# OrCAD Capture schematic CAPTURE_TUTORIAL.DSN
size A; title: Capture Walkthrough; rev: A; company: EMA Design Automation; note: EMA-12345678; note: 225 Tech park Dr; note: Rochester, NY
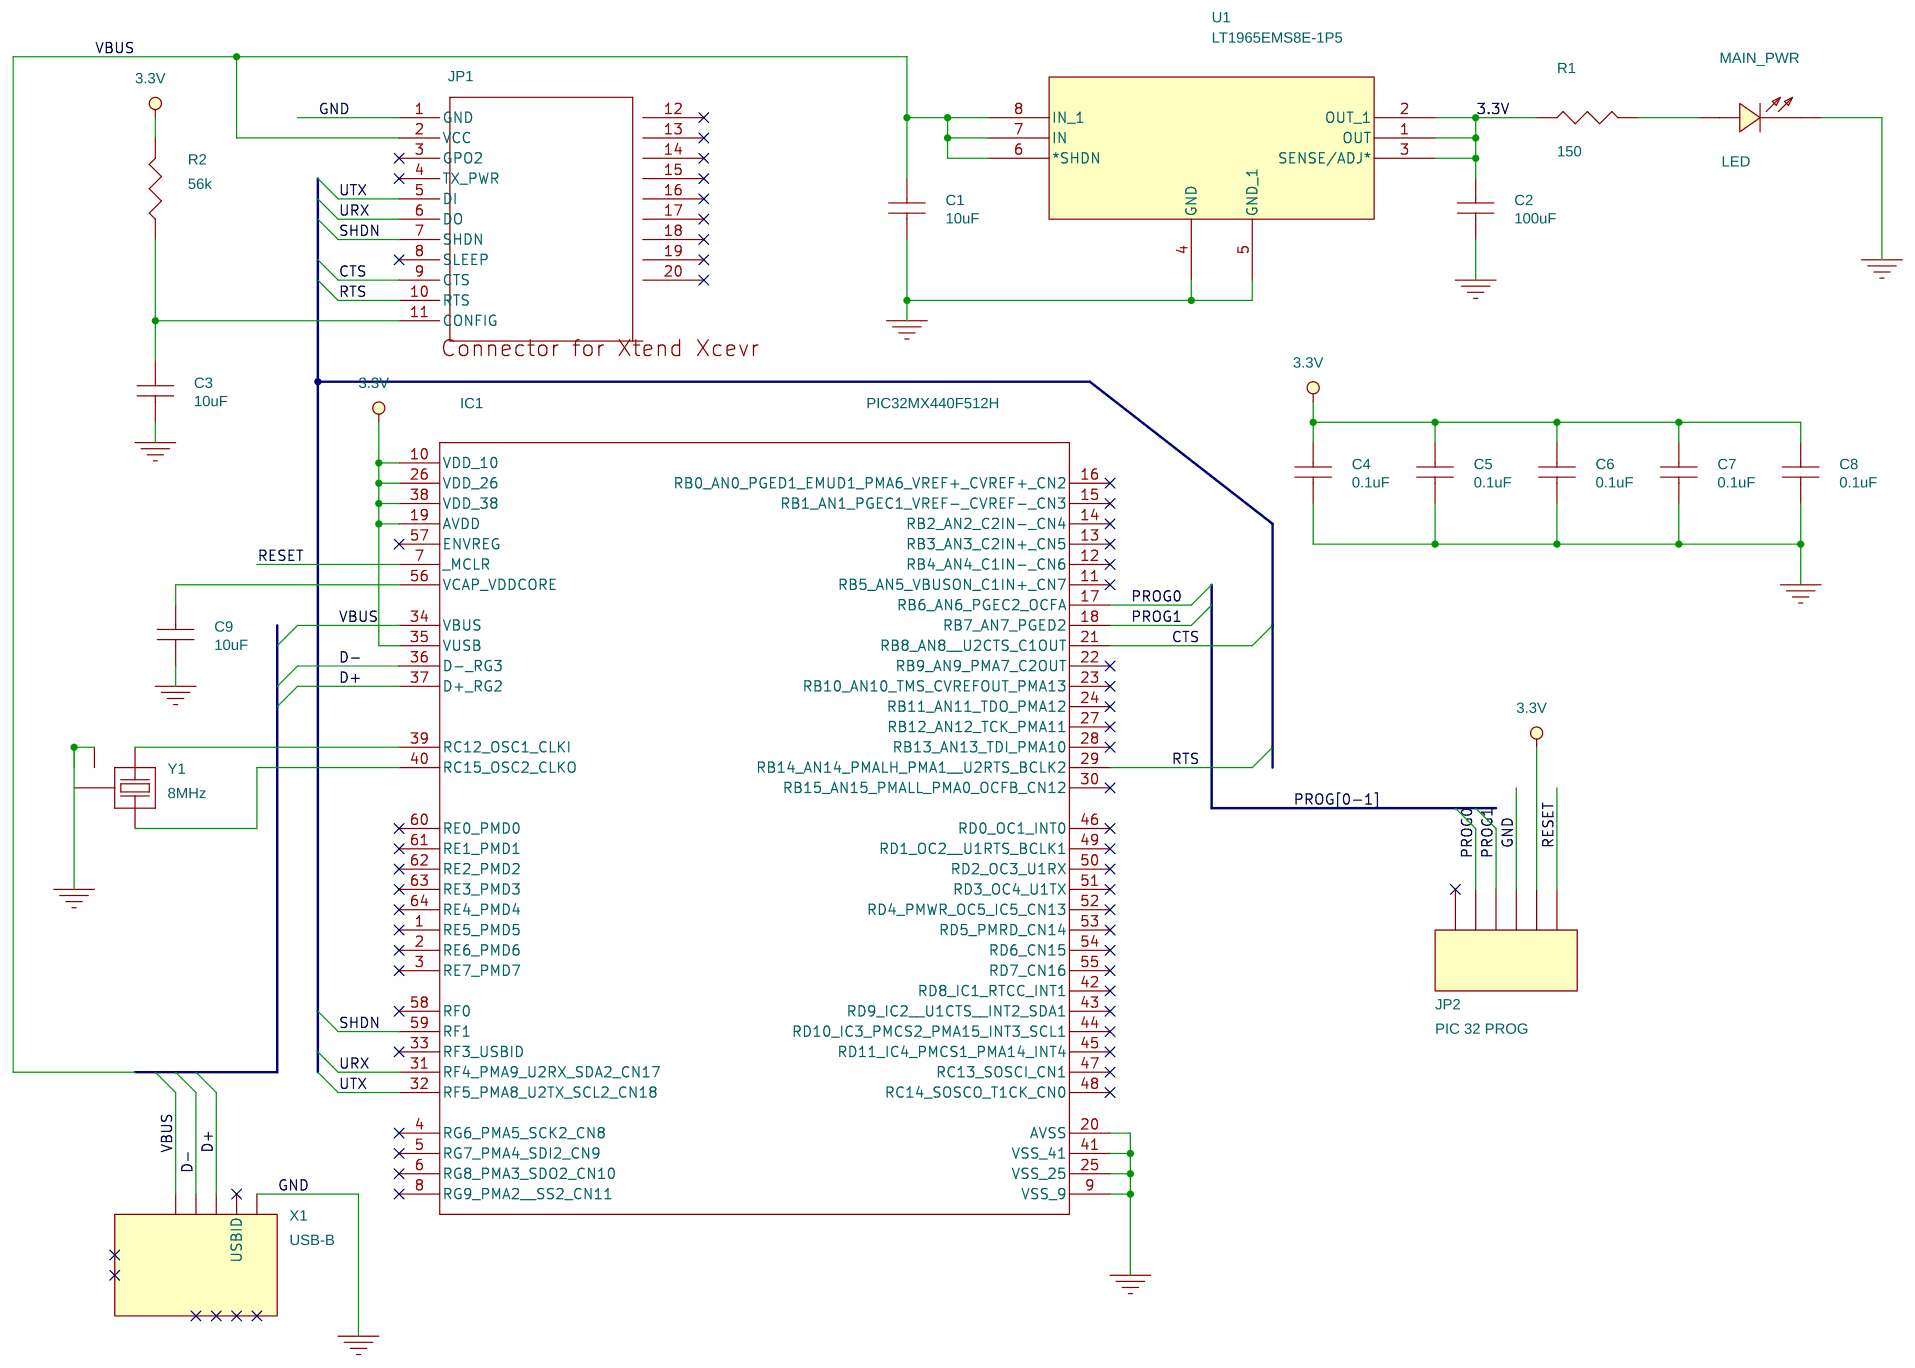
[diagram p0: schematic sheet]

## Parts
C1  10uF  [0402-CAP]
C2  100uF  [1210]
C3  10uF  [0402-CAP]
C4  0.1uF  [0402-CAP]
C5  0.1uF  [0402-CAP]
C6  0.1uF  [0402-CAP]
C7  0.1uF  [0402-CAP]
C8  0.1uF  [0402-CAP]
C9  10uF  [0402-CAP]
IC1  PIC32MX440F512H  [sqfp-s-10x10-64]
JP1  XTEND-DIGI-MODEM  [xtend-digi-modem]
JP2  PIC 32 PROG  [1x06_lock]
MAIN_PWR  LED  [LED_LNJ]
R1  150  [0402-RES]
R2  56k  [0402-RES]
U1  LT1965EMS8E-1P5  [MSOP_8_ADI]
X1  USB-B  [USB-MICROB]
Y1  8MHz  [crystal-smd]

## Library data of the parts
C1 C3 C9 = CAP_NP: Manufacturer Name: Murata; Manufacturer Part Number: GRJ155R60J106ME11D; Vendor: DigiKey
C2 = CAP_NP: Manufacturer Name: Murata; Manufacturer Part Number: GRM32EC80J107ME20L; Vendor: DigiKey
C4-C8 = CAP_NP: Manufacturer Name: Samsung; Manufacturer Part Number: CL05F104ZO5NNNC; ROOM: PWR_3.3V; Vendor: DigiKey
IC1 = PIC32MX440F512H: Manufacturer Name: Microchip; Manufacturer Part Number: PIC32MX440F512H-MXR; Vendor: DigiKey
JP1 = XTEND-DIGI-MODEM: Vendor: DigiKey
JP2 = M06_LOCK: Manufacturer Name: TE Connectivity; Manufacturer Part Number: 640456-6; Vendor: DigiKey
MAIN_PWR = LED: Manufacturer Name: LITE-ON, INC; Manufacturer Part Number: LTST-C191KRKT; Vendor: DigiKey
R1 = RESISTOR: Manufacturer Name: Samsung; Manufacturer Part Number: RCS1005F151CS; Vendor: DigiKey
R2 = RESISTOR: Manufacturer Name: Panasonic; Manufacturer Part Number: ERA-2AEB563X; Vendor: DigiKey
U1 = LT1965EMS8E-1P5_1: Distributor Id: Digi-Key; Distributor Part Number: 2156-LT1965EMS8E-1.5-600060-ND; Manufacturer Name: Analog Devices Inc; Manufacturer Part Number: LT1965EMS8E-1.5; Part Number: LT1965EMS8E-1.5; Source Id: UL; Vendor: DigiKey
X1 = USB-MICROB: Manufacturer Name: Amphenol; Manufacturer Part Number: 10104110-0001LF; Vendor: DigiKey
Y1 = CRYSTAL: Manufacturer Name: Abracon; Manufacturer Part Number: ABM3-8MHZ-CL-R500-B1G; Vendor: DigiKey

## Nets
3.3V: C2.1 C4.1 C5.1 C6.1 C7.1 C8.1 IC1.10(VDD) IC1.19(AVDD) IC1.26(VDD) IC1.35(VUSB) IC1.38(VDD) JP2.2 R1.1 R2.2 U1.1(OUT) U1.2(OUT_1) U1.3(SENSE/ADJ*)
GND: C1.2 C2.2 C3.2 C4.2 C5.2 C6.2 C7.2 C8.2 C9.2 IC1.9(VSS) IC1.20(AVSS) IC1.25(VSS) IC1.41(VSS) JP1.1(GND) JP2.3 MAIN_PWR.1(CATHODE) U1.4(GND) U1.5(GND_1) X1.GND Y1.2(GND) Y1.4(GND)
VBUS: C1.1 IC1.34(VBUS) JP1.2(VCC) U1.6(*SHDN) U1.7(IN) U1.8(IN_1) X1.VBUS
CTS: IC1.21(RB8_AN8__U2CTS_C1OUT) JP1.9(CTS)
D+: IC1.37(D+_RG2) X1.D+
D-: IC1.36(D-_RG3) X1.D-
PROG0: IC1.17(RB6_AN6_PGEC2_OCFA) JP2.5
PROG1: IC1.18(RB7_AN7_PGED2) JP2.4
RESET: IC1.7(_MCLR) JP2.1
RTS: IC1.29(RB14_AN14_PMALH_PMA1__U2RTS_BCLK2) JP1.10(RTS)
SHDN: IC1.59(RF1) JP1.7(SHDN)
URX: IC1.31(RF4_PMA9_U2RX_SDA2_CN17) JP1.6(DO)
UTX: IC1.32(RF5_PMA8_U2TX_SCL2_CN18) JP1.5(DI)
N01899: MAIN_PWR.2(ANODE) R1.2
N02098: IC1.39(RC12_OSC1_CLKI) Y1.1
N02102: IC1.40(RC15_OSC2_CLKO) Y1.3
N02114: C9.1 IC1.56(VCAP_VDDCORE)
N02189: C3.1 JP1.11(CONFIG) R2.1

Not connected (* = marked no-connect by the designer): IC1 1(RE5_PMD5)* 2(RE6_PMD6)* 3(RE7_PMD7)* 4(RG6_PMA5_SCK2_CN8)* 5(RG7_PMA4_SDI2_CN9)* 6(RG8_PMA3_SDO2_CN10)* 8(RG9_PMA2__SS2_CN11)* 11(RB5_AN5_VBUSON_C1IN+_CN7)* 12(RB4_AN4_C1IN-_CN6)* 13(RB3_AN3_C2IN+_CN5)* 14(RB2_AN2_C2IN-_CN4)* 15(RB1_AN1_PGEC1_VREF-_CVREF-_CN3)* 16(RB0_AN0_PGED1_EMUD1_PMA6_VREF+_CVREF+_CN2)* 22(RB9_AN9_PMA7_C2OUT)* 23(RB10_AN10_TMS_CVREFOUT_PMA13)* 24(RB11_AN11_TDO_PMA12)* 27(RB12_AN12_TCK_PMA11)* 28(RB13_AN13_TDI_PMA10)* 30(RB15_AN15_PMALL_PMA0_OCFB_CN12)* 33(RF3_USBID)* 42(RD8_IC1_RTCC_INT1)* 43(RD9_IC2__U1CTS__INT2_SDA1)* 44(RD10_IC3_PMCS2_PMA15_INT3_SCL1)* 45(RD11_IC4_PMCS1_PMA14_INT4)* 46(RD0_OC1_INT0)* 47(RC13_SOSCI_CN1)* 48(RC14_SOSCO_T1CK_CN0)* 49(RD1_OC2__U1RTS_BCLK1)* 50(RD2_OC3_U1RX)* 51(RD3_OC4_U1TX)* 52(RD4_PMWR_OC5_IC5_CN13)* 53(RD5_PMRD_CN14)* 54(RD6_CN15)* 55(RD7_CN16)* 57(ENVREG)* 58(RF0)* 60(RE0_PMD0)* 61(RE1_PMD1)* 62(RE2_PMD2)* 63(RE3_PMD3)* 64(RE4_PMD4)*; JP1 3(GPO2)* 4(TX_PWR)* 8(SLEEP)* 12* 13* 14* 15* 16* 17* 18* 19* 20*; JP2 6*; X1 ID(USBID)* MT1* MT2* MT3* MT4* P_1* P_2*
